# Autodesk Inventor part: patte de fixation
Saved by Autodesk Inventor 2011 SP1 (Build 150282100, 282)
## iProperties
Created: 2010-12
Part Number: patte de fixation
Document SubType Name: Modeling
Designer: eric
Density: 1 g/cm^3
Author: eric
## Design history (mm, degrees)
feature "Base1"
node "Solide1"
node "Corps solides"
node "Corps surfaciques"
